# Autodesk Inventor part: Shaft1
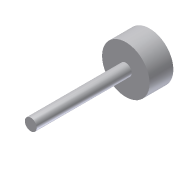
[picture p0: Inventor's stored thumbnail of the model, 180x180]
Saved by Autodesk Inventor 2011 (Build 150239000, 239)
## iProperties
Created: 2007-12
Part Number: Shaft1
Document SubType Name: Modeling
Density: 1 g/cm^3
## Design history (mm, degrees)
sketch "Sketch1"
  geometry: C1 r 1.587 at (-2.076, 36.443)
  constraints: 1 centre point
  dimensions: "d0" = 3.175 diameter of C1
extrude "Extrusion1" new body sketch "Sketch1" distance "d1" = 25.4; taper "d2" = 0 deg
sketch "Sketch2"
  geometry: C1 r 1.587 at (0, 0) reference; C2 r 6.35 at (0, 0)
  constraints: 1 centre point, 1 coincident
  dimensions: "d3" = 12.7 diameter of C2
extrude "Extrusion2" join sketch "Sketch2" distance "d4" = 6.35; taper "d5" = 0 deg
body "Solid1"
